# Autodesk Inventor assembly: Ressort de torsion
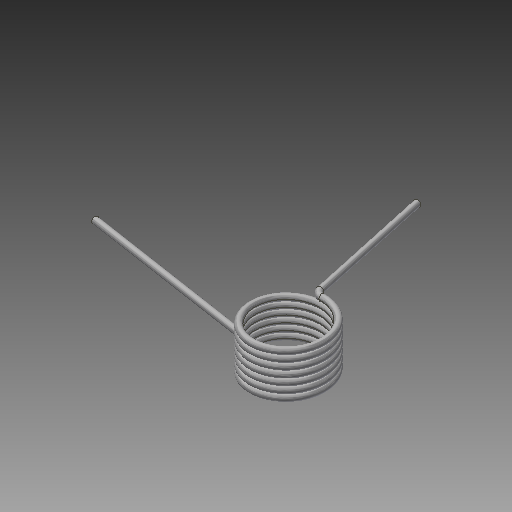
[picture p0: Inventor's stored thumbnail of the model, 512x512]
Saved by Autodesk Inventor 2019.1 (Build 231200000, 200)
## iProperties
Created: 2018-06
Part Number: Ressort de torsion
Document SubType Name: Assembly
Designer: Fabian Perrée
ClientObjectVersion: 1
Author: Fabian Perrée
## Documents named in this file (2)
- C:\Users\Fabian\Google Drive\04_CAO\01_Inventor\01_Fichiers_exercice_Inventor\01_Definitif\Capteur\Ens_levier\Design Accelerator\Ressort de torsion1.iam
- C:\Users\Fabian\Google Drive\04_CAO\01_Inventor\01_Fichiers_exercice_Inventor\01_Definitif\Capteur\Ens_levier\Design Accelerator\Ressort de torsion1.ipt
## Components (1 placed, 1 different names)
1. Ressort de torsion:1
